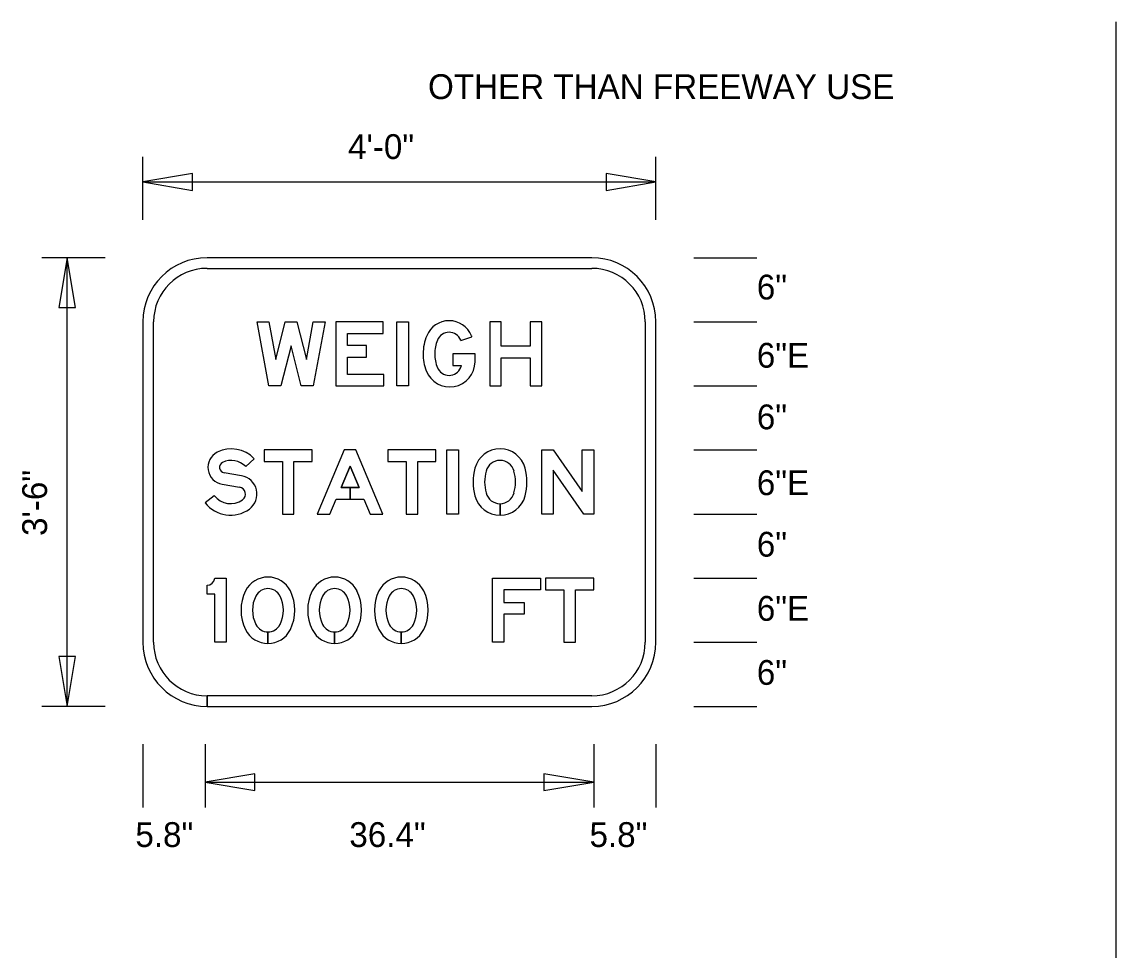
# Model space of a CAD drawing. Extents: x 0 to 770, y 0 to 495.
# Drawn here: x 423.5 to 577.8, y 364 to 495 of the extents above; entities that cross this region are included whole.
import ezdxf

# ---------------------------------------------------------------- set-up
doc = ezdxf.new("R2010")
doc.units = 0
for name, color, linetype in [('Dimension', 7, 'Continuous'), ('GSBWFill', 7, 'Continuous'), ('GSColorFill', 7, 'Continuous'), ('GSDims', 7, 'Continuous'), ('GSOutline', 7, 'Continuous'), ('SheetLines_dp', 7, 'Continuous'), ('TextStructures', 7, 'Continuous')]:
    doc.layers.add(name, color=color, linetype=linetype)

msp = doc.modelspace()

# ---------------------------------------------------------------- linework, layer by layer
at = {"layer": 'Dimension'}
for points in [[(440.52, 472.41), (447.54, 471.22), (447.54, 473.59)], [(512.88, 472.41), (505.86, 473.59), (505.86, 471.22)], [(429.84, 461.72), (428.65, 454.7), (431.03, 454.7)], [(429.84, 398.41), (431.03, 405.43), (428.65, 405.43)], [(449.3, 387.73), (456.31, 386.54), (456.31, 388.91)], [(504.11, 387.73), (497.09, 388.91), (497.09, 386.54)]]:
    msp.add_lwpolyline(points, close=True, dxfattribs=at)
at = {"layer": 'GSBWFill'}
for p, q in [((503.84, 461.72), (449.57, 461.72)), ((503.84, 461.72), (449.57, 461.72)), ((449.57, 460.21), (503.84, 460.21)), ((440.52, 452.68), (440.52, 407.45)), ((440.52, 452.68), (440.52, 407.45)), ((442.03, 407.45), (442.03, 452.68)), ((511.37, 452.68), (511.37, 407.45)), ((512.88, 407.45), (512.88, 452.68)), ((512.88, 407.45), (512.88, 452.68)), ((485.39, 450.02), (486.92, 450.57)), ((487.37, 447.04), (487.37, 448.15)), ((455.02, 432.24), (456.22, 433.34)), ((454.44, 430.96), (451.97, 431.38)), ((451.7, 429.77), (454.17, 429.35)), ((450.59, 428.14), (449.3, 427.15)), ((490.9, 425.38), (490.9, 427.01)), ((490.9, 427.01), (490.9, 425.38)), ((458.16, 408.92), (458.16, 407.3)), ((458.16, 407.3), (458.16, 408.92)), ((467.57, 408.92), (467.57, 407.3)), ((467.57, 407.3), (467.57, 408.92)), ((476.97, 408.92), (476.97, 407.3)), ((476.97, 407.3), (476.97, 408.92)), ((449.57, 398.41), (449.57, 399.92)), ((503.84, 399.92), (449.58, 399.92)), ((449.58, 399.92), (449.58, 398.41)), ((449.57, 398.41), (503.84, 398.41)), ((449.58, 398.41), (503.84, 398.41))]:
    msp.add_line(p, q, dxfattribs=at)
for points in [[(461.42, 449.29), (459.99, 443.63), (458.27, 443.63), (456.62, 452.68), (458.28, 452.68), (459.25, 447.35), (460.59, 452.68), (462.24, 452.68), (463.58, 447.35), (464.55, 452.68), (466.21, 452.68), (464.56, 443.63), (462.84, 443.63)], [(474.53, 445.26), (469.38, 445.26), (469.38, 447.69), (472.04, 447.69), (472.04, 449.32), (469.38, 449.32), (469.38, 451.05), (474.4, 451.05), (474.4, 452.68), (467.75, 452.68), (467.75, 443.63), (474.53, 443.63)], [(476.34, 443.63), (476.34, 452.68), (477.97, 452.68), (477.97, 443.63)], [(495.15, 449.24), (491.08, 449.24), (491.08, 452.68), (489.45, 452.68), (489.45, 443.63), (491.08, 443.63), (491.08, 447.61), (495.15, 447.61), (495.15, 443.63), (496.78, 443.63), (496.78, 452.68), (495.15, 452.68)], [(457.62, 432.96), (460.2, 432.96), (460.2, 425.54), (461.82, 425.54), (461.82, 432.96), (464.4, 432.96), (464.4, 434.59), (457.62, 434.59)], [(471.01, 429.3), (469.74, 429.3), (469.74, 427.67), (471.69, 427.67), (472.58, 425.54), (474.35, 425.54), (470.55, 434.59), (468.92, 434.59), (465.12, 425.54), (466.89, 425.54), (467.78, 427.67), (469.74, 427.67), (469.74, 429.3), (468.47, 429.3), (469.74, 432.32)], [(475.07, 432.96), (477.65, 432.96), (477.65, 425.54), (479.28, 425.54), (479.28, 432.96), (481.86, 432.96), (481.86, 434.59), (475.07, 434.59)], [(483.39, 425.54), (483.39, 434.59), (485.02, 434.59), (485.02, 425.54)], [(504.11, 434.59), (504.11, 425.54), (502.7, 425.54), (498.41, 431.74), (498.41, 425.54), (496.78, 425.54), (496.78, 434.59), (498.41, 434.59), (502.48, 428.73), (502.48, 434.59)], [(491.44, 411.43), (491.44, 407.45), (489.82, 407.45), (489.82, 416.5), (496.6, 416.5), (496.6, 414.87), (491.44, 414.87), (491.44, 413.06), (494.29, 413.06), (494.29, 411.43)], [(497.32, 414.87), (499.9, 414.87), (499.9, 407.45), (501.53, 407.45), (501.53, 414.87), (504.11, 414.87), (504.11, 416.5), (497.32, 416.5)]]:
    msp.add_lwpolyline(points, close=True, dxfattribs=at)
for points in [[(487.37, 448.15), (484.25, 448.15), (484.25, 446.53), (485.48, 446.53)], [(452.28, 407.45), (450.65, 407.45), (450.65, 414.24), (449.57, 414.24), (449.57, 415.5)], [(450.65, 416.5), (452.28, 416.5), (452.28, 407.45)]]:
    msp.add_lwpolyline(points, dxfattribs=at)
for centre, radius, start, end in [((449.57, 452.68), 9.04, 90, 180), ((449.57, 452.68), 9.04, 90, 180), ((503.84, 452.68), 9.04, 0, 90), ((503.84, 452.68), 9.04, 0, 90), ((449.57, 452.68), 7.54, 90, 180), ((503.84, 452.68), 7.54, 0, 90), ((483.71, 449.42), 3.41, 22.4256, 157.5744), ((486.79, 448.15), 6.74, 157.5744, 180), ((483.71, 449.42), 1.78, 22.4256, 157.5744), ((480.64, 448.15), 6.74, 21.0425, 22.4256), ((486.79, 448.15), 5.11, 157.5744, 180), ((480.64, 448.15), 5.11, 21.4721, 22.4256), ((486.79, 448.15), 6.74, 180, 200.6303), ((486.79, 448.15), 5.11, 180, 202.4256), ((483.81, 447.04), 3.56, 200.6303, 0), ((483.71, 446.89), 1.78, 202.4256, 337.5744), ((480.64, 448.15), 5.11, 337.5744, 341.4227), ((452.1, 432.13), 2.4, 116.9123, 260.4087), ((453, 430.36), 4.39, 42.8759, 116.9123), ((490.9, 431.08), 3.67, 14.9618, 165.0382), ((452.1, 432.13), 0.769, 116.9123, 260.4087), ((453, 430.36), 2.76, 42.8759, 116.9123), ((490.9, 431.08), 2.04, 14.9618, 165.0382), ((454, 428.37), 2.62, 306.123, 80.4087), ((494.7, 430.07), 7.6, 165.0382, 194.9618), ((494.7, 430.07), 5.97, 165.0382, 194.9618), ((487.1, 430.07), 5.97, 345.0382, 14.9618), ((487.1, 430.07), 7.6, 345.0382, 14.9618), ((454, 428.37), 0.995, 306.123, 80.4087), ((452.88, 429.91), 2.89, 217.5895, 306.123), ((490.9, 429.05), 3.67, 194.9618, 270), ((490.9, 429.05), 2.04, 194.9618, 270), ((490.9, 429.05), 2.04, 270.0127, 345.0382), ((490.9, 429.05), 3.67, 270.0071, 345.0382), ((452.88, 429.91), 4.52, 217.5895, 306.123), ((449.57, 416.59), 1.09, 270, 355.0209), ((467.57, 413.13), 3.53, 26.481, 153.519), ((476.97, 413.13), 3.53, 26.481, 153.519), ((469.88, 411.98), 6.11, 153.519, 206.481), ((469.88, 411.98), 4.49, 153.519, 206.481), ((467.57, 413.13), 1.9, 26.481, 153.519), ((465.25, 411.98), 4.49, 333.519, 26.481), ((465.25, 411.98), 6.11, 333.519, 26.481), ((479.29, 411.98), 6.11, 153.519, 206.481), ((479.29, 411.98), 4.49, 153.519, 206.481), ((476.97, 413.13), 1.9, 26.481, 153.519), ((474.66, 411.98), 4.49, 333.519, 26.481), ((474.66, 411.98), 6.11, 333.519, 26.481), ((467.57, 410.82), 3.53, 206.481, 270), ((467.57, 410.82), 1.9, 206.481, 270), ((467.57, 410.82), 1.9, 270.0136, 333.519), ((467.57, 410.82), 3.53, 270.0073, 333.519), ((476.97, 410.82), 3.53, 206.481, 270), ((476.97, 410.82), 1.9, 206.481, 270), ((476.97, 410.82), 1.9, 270.0136, 333.519), ((476.97, 410.82), 3.53, 270.0073, 333.519), ((449.57, 407.45), 9.04, 180, 270), ((449.57, 407.45), 9.04, 180, 270), ((449.57, 407.45), 7.54, 180, 270), ((503.84, 407.45), 9.04, 270, 0), ((503.84, 407.45), 7.54, 270, 0), ((503.84, 407.45), 9.04, 270, 0)]:
    msp.add_arc(centre, radius, start, end, dxfattribs=at)
for centre, major_axis, start_param, end_param in [((458.16, 413.13), (0, 3.53), 5.17457, 7.3918), ((460.47, 411.98), (0, 6.11), 1.108615, 2.032978), ((460.47, 411.98), (0, 4.49), 1.108615, 2.032978), ((458.16, 413.13), (0, 1.9), 5.17457, 7.3918), ((455.85, 411.98), (0, 4.49), 4.250208, 5.17457), ((455.85, 411.98), (0, 6.11), 4.250208, 5.17457), ((458.16, 410.82), (0, 3.53), 2.032978, 3.141593), ((458.16, 410.82), (0, 1.9), 2.032978, 3.141593), ((458.16, 410.82), (0, 1.9), 3.141831, 4.250208), ((458.16, 410.82), (0, 3.53), 3.141721, 4.250208)]:
    msp.add_ellipse(centre, major_axis=major_axis, ratio=0.999994, start_param=start_param, end_param=end_param, dxfattribs=at)
at = {"layer": 'GSColorFill'}
for p, q in [((485.39, 450.02), (486.92, 450.57)), ((487.37, 447.04), (487.37, 448.15)), ((455.02, 432.24), (456.22, 433.34)), ((454.44, 430.96), (451.97, 431.38)), ((451.7, 429.77), (454.17, 429.35)), ((450.59, 428.14), (449.3, 427.15)), ((490.9, 425.38), (490.9, 427.01)), ((490.9, 427.01), (490.9, 425.38)), ((458.16, 408.92), (458.16, 407.3)), ((458.16, 407.3), (458.16, 408.92)), ((467.57, 408.92), (467.57, 407.3)), ((467.57, 407.3), (467.57, 408.92)), ((476.97, 408.92), (476.97, 407.3)), ((476.97, 407.3), (476.97, 408.92))]:
    msp.add_line(p, q, dxfattribs=at)
for points in [[(461.42, 449.29), (459.99, 443.63), (458.27, 443.63), (456.62, 452.68), (458.28, 452.68), (459.25, 447.35), (460.59, 452.68), (462.24, 452.68), (463.58, 447.35), (464.55, 452.68), (466.21, 452.68), (464.56, 443.63), (462.84, 443.63)], [(474.53, 445.26), (469.38, 445.26), (469.38, 447.69), (472.04, 447.69), (472.04, 449.32), (469.38, 449.32), (469.38, 451.05), (474.4, 451.05), (474.4, 452.68), (467.75, 452.68), (467.75, 443.63), (474.53, 443.63)], [(476.34, 443.63), (476.34, 452.68), (477.97, 452.68), (477.97, 443.63)], [(495.15, 449.24), (491.08, 449.24), (491.08, 452.68), (489.45, 452.68), (489.45, 443.63), (491.08, 443.63), (491.08, 447.61), (495.15, 447.61), (495.15, 443.63), (496.78, 443.63), (496.78, 452.68), (495.15, 452.68)], [(457.62, 432.96), (460.2, 432.96), (460.2, 425.54), (461.82, 425.54), (461.82, 432.96), (464.4, 432.96), (464.4, 434.59), (457.62, 434.59)], [(471.01, 429.3), (469.74, 429.3), (469.74, 427.67), (471.69, 427.67), (472.58, 425.54), (474.35, 425.54), (470.55, 434.59), (468.92, 434.59), (465.12, 425.54), (466.89, 425.54), (467.78, 427.67), (469.74, 427.67), (469.74, 429.3), (468.47, 429.3), (469.74, 432.32)], [(475.07, 432.96), (477.65, 432.96), (477.65, 425.54), (479.28, 425.54), (479.28, 432.96), (481.86, 432.96), (481.86, 434.59), (475.07, 434.59)], [(483.39, 425.54), (483.39, 434.59), (485.02, 434.59), (485.02, 425.54)], [(504.11, 434.59), (504.11, 425.54), (502.7, 425.54), (498.41, 431.74), (498.41, 425.54), (496.78, 425.54), (496.78, 434.59), (498.41, 434.59), (502.48, 428.73), (502.48, 434.59)], [(491.44, 411.43), (491.44, 407.45), (489.82, 407.45), (489.82, 416.5), (496.6, 416.5), (496.6, 414.87), (491.44, 414.87), (491.44, 413.06), (494.29, 413.06), (494.29, 411.43)], [(497.32, 414.87), (499.9, 414.87), (499.9, 407.45), (501.53, 407.45), (501.53, 414.87), (504.11, 414.87), (504.11, 416.5), (497.32, 416.5)]]:
    msp.add_lwpolyline(points, close=True, dxfattribs=at)
for points in [[(487.37, 448.15), (484.25, 448.15), (484.25, 446.53), (485.48, 446.53)], [(452.28, 407.45), (450.65, 407.45), (450.65, 414.24), (449.57, 414.24), (449.57, 415.5)], [(450.65, 416.5), (452.28, 416.5), (452.28, 407.45)]]:
    msp.add_lwpolyline(points, dxfattribs=at)
for centre, radius, start, end in [((483.71, 449.42), 3.41, 22.4256, 157.5744), ((486.79, 448.15), 6.74, 157.5744, 180), ((483.71, 449.42), 1.78, 22.4256, 157.5744), ((480.64, 448.15), 6.74, 21.0425, 22.4256), ((486.79, 448.15), 5.11, 157.5744, 180), ((480.64, 448.15), 5.11, 21.4721, 22.4256), ((486.79, 448.15), 6.74, 180, 200.6303), ((486.79, 448.15), 5.11, 180, 202.4256), ((483.81, 447.04), 3.56, 200.6303, 0), ((483.71, 446.89), 1.78, 202.4256, 337.5744), ((480.64, 448.15), 5.11, 337.5744, 341.4227), ((452.1, 432.13), 2.4, 116.9123, 260.4087), ((453, 430.36), 4.39, 42.8759, 116.9123), ((490.9, 431.08), 3.67, 14.9618, 165.0382), ((452.1, 432.13), 0.769, 116.9123, 260.4087), ((453, 430.36), 2.76, 42.8759, 116.9123), ((490.9, 431.08), 2.04, 14.9618, 165.0382), ((454, 428.37), 2.62, 306.123, 80.4087), ((494.7, 430.07), 7.6, 165.0382, 194.9618), ((494.7, 430.07), 5.97, 165.0382, 194.9618), ((487.1, 430.07), 5.97, 345.0382, 14.9618), ((487.1, 430.07), 7.6, 345.0382, 14.9618), ((454, 428.37), 0.995, 306.123, 80.4087), ((452.88, 429.91), 2.89, 217.5895, 306.123), ((490.9, 429.05), 3.67, 194.9618, 270), ((490.9, 429.05), 2.04, 194.9618, 270), ((490.9, 429.05), 2.04, 270.0127, 345.0382), ((490.9, 429.05), 3.67, 270.0071, 345.0382), ((452.88, 429.91), 4.52, 217.5895, 306.123), ((449.57, 416.59), 1.09, 270, 355.0209), ((467.57, 413.13), 3.53, 26.481, 153.519), ((476.97, 413.13), 3.53, 26.481, 153.519), ((469.88, 411.98), 6.11, 153.519, 206.481), ((469.88, 411.98), 4.49, 153.519, 206.481), ((467.57, 413.13), 1.9, 26.481, 153.519), ((465.25, 411.98), 4.49, 333.519, 26.481), ((465.25, 411.98), 6.11, 333.519, 26.481), ((479.29, 411.98), 6.11, 153.519, 206.481), ((479.29, 411.98), 4.49, 153.519, 206.481), ((476.97, 413.13), 1.9, 26.481, 153.519), ((474.66, 411.98), 4.49, 333.519, 26.481), ((474.66, 411.98), 6.11, 333.519, 26.481), ((467.57, 410.82), 3.53, 206.481, 270), ((467.57, 410.82), 1.9, 206.481, 270), ((467.57, 410.82), 1.9, 270.0136, 333.519), ((467.57, 410.82), 3.53, 270.0073, 333.519), ((476.97, 410.82), 3.53, 206.481, 270), ((476.97, 410.82), 1.9, 206.481, 270), ((476.97, 410.82), 1.9, 270.0136, 333.519), ((476.97, 410.82), 3.53, 270.0073, 333.519)]:
    msp.add_arc(centre, radius, start, end, dxfattribs=at)
for centre, major_axis, start_param, end_param in [((458.16, 413.13), (0, 3.53), 5.17457, 7.3918), ((460.47, 411.98), (0, 6.11), 1.108615, 2.032978), ((460.47, 411.98), (0, 4.49), 1.108615, 2.032978), ((458.16, 413.13), (0, 1.9), 5.17457, 7.3918), ((455.85, 411.98), (0, 4.49), 4.250208, 5.17457), ((455.85, 411.98), (0, 6.11), 4.250208, 5.17457), ((458.16, 410.82), (0, 3.53), 2.032978, 3.141593), ((458.16, 410.82), (0, 1.9), 2.032978, 3.141593), ((458.16, 410.82), (0, 1.9), 3.141831, 4.250208), ((458.16, 410.82), (0, 3.53), 3.141721, 4.250208)]:
    msp.add_ellipse(centre, major_axis=major_axis, ratio=0.999994, start_param=start_param, end_param=end_param, dxfattribs=at)
at = {"layer": 'GSDims'}
for p, q in [((440.52, 467.06), (440.52, 475.97)), ((512.88, 467.06), (512.88, 475.97)), ((440.52, 472.41), (512.88, 472.41)), ((435.18, 461.72), (426.28, 461.72)), ((429.84, 398.41), (429.84, 461.72)), ((518.22, 461.72), (527.12, 461.72)), ((518.22, 452.68), (527.12, 452.68)), ((518.22, 452.68), (527.12, 452.68)), ((518.22, 443.63), (527.12, 443.63)), ((518.22, 443.63), (527.12, 443.63)), ((518.22, 434.59), (527.12, 434.59)), ((518.22, 434.59), (527.12, 434.59)), ((518.22, 425.54), (527.12, 425.54)), ((518.22, 425.54), (527.12, 425.54)), ((518.22, 416.5), (527.12, 416.5)), ((518.22, 416.5), (527.12, 416.5)), ((518.22, 407.45), (527.12, 407.45)), ((518.22, 407.45), (527.12, 407.45)), ((435.18, 398.41), (426.28, 398.41)), ((518.22, 398.41), (527.12, 398.41)), ((440.52, 393.07), (440.52, 384.16)), ((449.3, 393.07), (449.3, 384.16)), ((449.3, 393.07), (449.3, 384.16)), ((504.11, 393.07), (504.11, 384.16)), ((504.11, 393.07), (504.11, 384.16)), ((512.88, 393.07), (512.88, 384.16)), ((449.3, 387.73), (504.11, 387.73))]:
    msp.add_line(p, q, dxfattribs=at)
at = {"layer": 'GSOutline'}
for p, q in [((485.39, 450.02), (486.92, 450.57)), ((487.37, 447.04), (487.37, 448.15)), ((455.02, 432.24), (456.22, 433.34)), ((454.44, 430.96), (451.97, 431.38)), ((451.7, 429.77), (454.17, 429.35)), ((450.59, 428.14), (449.3, 427.15))]:
    msp.add_line(p, q, dxfattribs=at)
for points in [[(461.42, 449.29), (459.99, 443.63), (458.27, 443.63), (456.62, 452.68), (458.28, 452.68), (459.25, 447.35), (460.59, 452.68), (462.24, 452.68), (463.58, 447.35), (464.55, 452.68), (466.21, 452.68), (464.56, 443.63), (462.84, 443.63)], [(474.53, 445.26), (469.38, 445.26), (469.38, 447.69), (472.04, 447.69), (472.04, 449.32), (469.38, 449.32), (469.38, 451.05), (474.4, 451.05), (474.4, 452.68), (467.75, 452.68), (467.75, 443.63), (474.53, 443.63)], [(476.34, 443.63), (476.34, 452.68), (477.97, 452.68), (477.97, 443.63)], [(495.15, 449.24), (491.08, 449.24), (491.08, 452.68), (489.45, 452.68), (489.45, 443.63), (491.08, 443.63), (491.08, 447.61), (495.15, 447.61), (495.15, 443.63), (496.78, 443.63), (496.78, 452.68), (495.15, 452.68)], [(457.62, 432.96), (460.2, 432.96), (460.2, 425.54), (461.82, 425.54), (461.82, 432.96), (464.4, 432.96), (464.4, 434.59), (457.62, 434.59)], [(467.78, 427.67), (471.69, 427.67), (472.58, 425.54), (474.35, 425.54), (470.55, 434.59), (468.92, 434.59), (465.12, 425.54), (466.89, 425.54)], [(475.07, 432.96), (477.65, 432.96), (477.65, 425.54), (479.28, 425.54), (479.28, 432.96), (481.86, 432.96), (481.86, 434.59), (475.07, 434.59)], [(483.39, 425.54), (483.39, 434.59), (485.02, 434.59), (485.02, 425.54)], [(504.11, 434.59), (504.11, 425.54), (502.7, 425.54), (498.41, 431.74), (498.41, 425.54), (496.78, 425.54), (496.78, 434.59), (498.41, 434.59), (502.48, 428.73), (502.48, 434.59)], [(471.01, 429.3), (469.74, 432.32), (468.47, 429.3)], [(491.44, 411.43), (491.44, 407.45), (489.82, 407.45), (489.82, 416.5), (496.6, 416.5), (496.6, 414.87), (491.44, 414.87), (491.44, 413.06), (494.29, 413.06), (494.29, 411.43)], [(497.32, 414.87), (499.9, 414.87), (499.9, 407.45), (501.53, 407.45), (501.53, 414.87), (504.11, 414.87), (504.11, 416.5), (497.32, 416.5)]]:
    msp.add_lwpolyline(points, close=True, dxfattribs=at)
for points in [[(487.37, 448.15), (484.25, 448.15), (484.25, 446.53), (485.48, 446.53)], [(452.28, 407.45), (450.65, 407.45), (450.65, 414.24), (449.57, 414.24), (449.57, 415.5)], [(450.65, 416.5), (452.28, 416.5), (452.28, 407.45)]]:
    msp.add_lwpolyline(points, dxfattribs=at)
for centre, radius, start, end in [((483.71, 449.42), 3.41, 22.4256, 157.5744), ((486.79, 448.15), 6.74, 157.5744, 180), ((483.71, 449.42), 1.78, 22.4256, 157.5744), ((480.64, 448.15), 6.74, 21.0425, 22.4256), ((486.79, 448.15), 5.11, 157.5744, 180), ((480.64, 448.15), 5.11, 21.4721, 22.4256), ((486.79, 448.15), 6.74, 180, 200.6303), ((486.79, 448.15), 5.11, 180, 202.4256), ((483.81, 447.04), 3.56, 200.6303, 0), ((483.71, 446.89), 1.78, 202.4256, 337.5744), ((480.64, 448.15), 5.11, 337.5744, 341.4227), ((452.1, 432.13), 2.4, 116.9123, 260.4087), ((453, 430.36), 4.39, 42.8759, 116.9123), ((490.9, 431.08), 3.67, 14.9618, 165.0382), ((452.1, 432.13), 0.769, 116.9123, 260.4087), ((453, 430.36), 2.76, 42.8759, 116.9123), ((490.9, 431.08), 2.04, 14.9618, 165.0382), ((454, 428.37), 2.62, 306.123, 80.4087), ((494.7, 430.07), 7.6, 165.0382, 194.9618), ((494.7, 430.07), 5.97, 165.0382, 194.9618), ((487.1, 430.07), 5.97, 345.0382, 14.9618), ((487.1, 430.07), 7.6, 345.0382, 14.9618), ((454, 428.37), 0.995, 306.123, 80.4087), ((452.88, 429.91), 2.89, 217.5895, 306.123), ((490.9, 429.05), 3.67, 194.9618, 345.0382), ((490.9, 429.05), 2.04, 194.9618, 345.0382), ((452.88, 429.91), 4.52, 217.5895, 306.123), ((449.57, 416.59), 1.09, 270, 355.0209), ((467.57, 413.13), 3.53, 26.481, 153.519), ((476.97, 413.13), 3.53, 26.481, 153.519), ((469.88, 411.98), 6.11, 153.519, 206.481), ((469.88, 411.98), 4.49, 153.519, 206.481), ((467.57, 413.13), 1.9, 26.481, 153.519), ((465.25, 411.98), 4.49, 333.519, 26.481), ((465.25, 411.98), 6.11, 333.519, 26.481), ((479.29, 411.98), 6.11, 153.519, 206.481), ((479.29, 411.98), 4.49, 153.519, 206.481), ((476.97, 413.13), 1.9, 26.481, 153.519), ((474.66, 411.98), 4.49, 333.519, 26.481), ((474.66, 411.98), 6.11, 333.519, 26.481), ((467.57, 410.82), 3.53, 206.481, 333.519), ((467.57, 410.82), 1.9, 206.481, 333.519), ((476.97, 410.82), 3.53, 206.481, 333.519), ((476.97, 410.82), 1.9, 206.481, 333.519)]:
    msp.add_arc(centre, radius, start, end, dxfattribs=at)
for centre, major_axis, start_param, end_param in [((458.16, 413.13), (0, 3.53), 5.17457, 7.3918), ((460.47, 411.98), (0, 6.11), 1.108615, 2.032978), ((460.47, 411.98), (0, 4.49), 1.108615, 2.032978), ((458.16, 413.13), (0, 1.9), 5.17457, 7.3918), ((455.85, 411.98), (0, 4.49), 4.250208, 5.17457), ((455.85, 411.98), (0, 6.11), 4.250208, 5.17457), ((458.16, 410.82), (0, 3.53), 2.032978, 4.250208), ((458.16, 410.82), (0, 1.9), 2.032978, 4.250208)]:
    msp.add_ellipse(centre, major_axis=major_axis, ratio=0.999994, start_param=start_param, end_param=end_param, dxfattribs=at)
at = {"layer": 'SheetLines_dp'}
msp.add_line((577.8, 0), (577.8, 495), dxfattribs=at)

# ---------------------------------------------------------------- texts
at = {"layer": 'TextStructures'}
for s, p in [('OTHER THAN FREEWAY USE', (480.74, 484.11)), ('4\'-0"', (469.46, 475.65)), ('6"', (527.12, 455.83)), ('6"E', (527.12, 446.2)), ('6"', (527.12, 437.51)), ('6"E', (527.12, 428.22)), ('6"', (527.12, 419.54)), ('6"E', (527.12, 410.49)), ('6"', (527.12, 401.45)), ('5.8"', (439.46, 378.57)), ('36.4"', (469.64, 378.57)), ('5.8"', (503.52, 378.57))]:
    msp.add_text(s, height=3.5, dxfattribs=at).set_placement(p)
msp.add_text('3\'-6"', height=3.5, rotation=90, dxfattribs=at).set_placement((427, 422.46))

doc.saveas('drawing.dxf')
